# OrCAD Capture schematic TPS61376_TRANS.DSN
size D; title: TPS61376 SIMULATION; note: 1
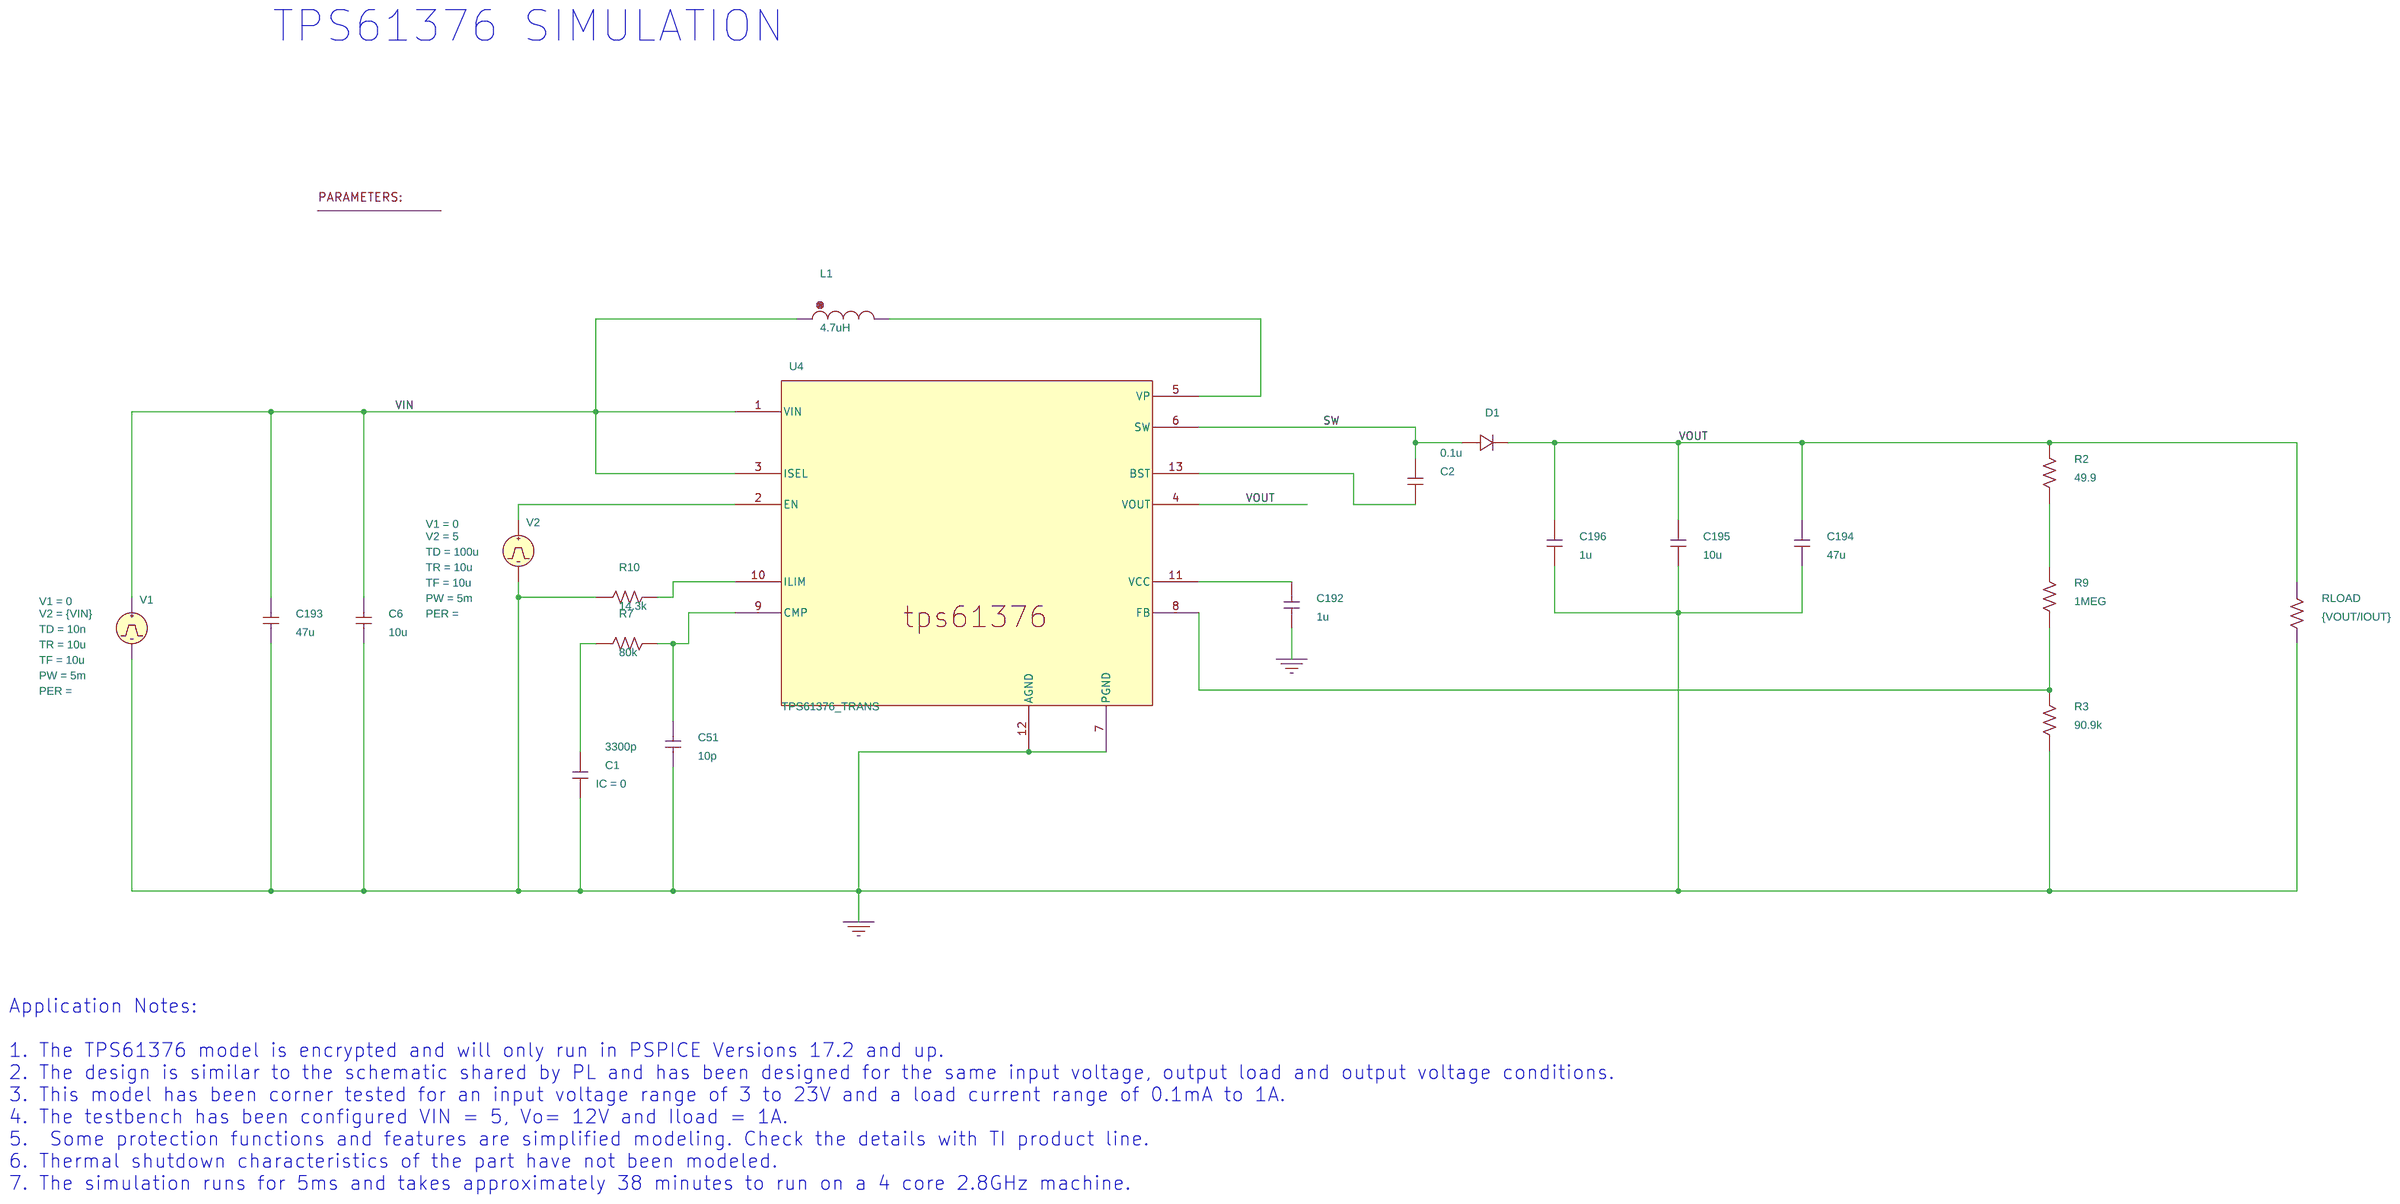
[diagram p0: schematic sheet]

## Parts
1  PARAM
C1  3300p  [RAD/CK05]
C2  0.1u  [RAD/CK05]
C6  10u  [RAD/CK05]
C51  10p  [RAD/CK05]
C192  1u  [cap196]
C193  47u  [RAD/CK05]
C194  47u  [RAD/CK05]
C195  10u  [RAD/CK05]
C196  1u  [RAD/CK05]
D1  Dbreak
L1  4.7uH  [DISC350x175LS200x100034]
R2  49.9  [AX/RC05]
R3  90.9k  [AX/RC05]
R7  80k  [AX/RC05]
R9  1MEG  [AX/RC05]
R10  14.3k  [AX/RC05]
RLOAD  {VOUT/IOUT}  [AX/RC05]
U4  TPS61376_TRANS
V1  VPULSE
V2  VPULSE

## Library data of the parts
1 = PARAM: SS: 0; VIN: 5; VOUT: 12
C1 C2 = C: IC: 0
C6 C51 C192-C196 = C
D1 = Dbreak
L1 = L
R2 R3 R7 R9 R10 RLOAD = R
U4 = TPS61376_TRANS_8
V1 = VPULSE: PW: 5m; TD: 10n; TF: 10u; TR: 10u; V1: 0; V2: {VIN}
V2 = VPULSE: PW: 5m; TD: 100u; TF: 10u; TR: 10u; V1: 0; V2: 5

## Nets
VIN: C6.1 C193.1 L1.1 U4.1(VIN) U4.3(ISEL) V1.1(+)
0: C1.2 C6.2 C51.2 C192.1 C193.2 C194.2 C195.2 C196.2 R3.1 R10.1 RLOAD.2 U4.7(PGND) U4.12(AGND) V1.2(-) V2.2(-)
SW: C2.1 D1.0(1) U4.6(SW)
VOUT: C194.1 C195.1 C196.1 D1.1(2) R2.2 RLOAD.1 U4.4(VOUT)
N02765: L1.2 U4.5(VP)
N02973: R2.1 R9.2
N03261: R10.2 U4.10(ILIM)
N03409: C51.1 R7.2 U4.9(CMP)
N03421: R3.2 R9.1 U4.8(FB)
N03433: C1.1 R7.1
N05505: C2.2 U4.13(BST)
N16775844: U4.2(EN) V2.1(+)
N16776175: C192.2 U4.11(VCC)

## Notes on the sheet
- TPS61376 SIMULATION
- Application Notes:
  1. The TPS61376 model is encrypted and will only run in PSPICE Versions 17.2 and up.
  2. The design is similar to the schematic shared by PL and has been designed for the same input voltage, output load and output voltage conditions.
  3. This model has been corner tested for an input voltage range of 3 to 23V and a load current range of 0.1mA to 1A.
  4. The testbench has been configured VIN = 5, Vo= 12V and Iload = 1A.
  5.  Some protection functions and features are simplified modeling. Check the details with TI product line.
  6. Thermal shutdown characteristics of the part have not been modeled.
  7. The simulation runs for 5ms and takes approximately 38 minutes to run on a 4 core 2.8GHz machine.
